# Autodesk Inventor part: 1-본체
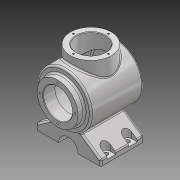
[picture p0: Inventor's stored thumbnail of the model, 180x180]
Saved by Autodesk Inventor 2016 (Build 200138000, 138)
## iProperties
Created: 2017-04
Part Number: 1-본체
Material: 알루미늄 6061
Document SubType Name: Modeling
Designer: H
Density: 2.7 g/cm^3
Appearance: 알루미늄 - 평지
Mass: 1664.44 g
Surface Area: 1066.89 cm^2
Volume: 616.46 cm^3
Author: H
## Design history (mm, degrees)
sketch "스케치2"
  geometry: L1 (-54, 50)-(54, 50); L2 (54, 50)-(54, 0); L3 (54, 0)-(-54, 0); L4 (-54, 0)-(-54, 50); A1 r 113 centre (-59, 0) between (54, 0) and (42.336, 50); 2 further points
  constraints: 8 end point, 2 parallel, 2 point on circle, 2 point on line, 1 centre point, 1 coincident, 1 horizontal, 1 midpoint, 1 perpendicular
  dimensions: "d1" = 113 radius of A1; "d2" = 100 diameter of L1 L3; "d128" = 108 horizontal distance of L2.end L1.start
revolve "회전1" sketch "스케치2" stored, may be unused: angle "d3" = 90 deg
node "작업 평면1"
sketch "스케치4"
  geometry: L1 (50, -54)-(-50, -54) reference; C1 r 38 at (0, -4); 2 further points
  constraints: 1 centre point, 1 midpoint, 1 vertical alignment
  dimensions: "d8" = 50 distance from line of L1 C1.centre; "d9" = 76 diameter of C1
extrude "돌출2" join sketch "스케치4" stored distance "d10" = 10; taper "d11" = 0 deg
sketch "스케치5"
  geometry: C1 r 38 at (0, 0); C2 r 50 at (0, 0) reference; 1 further point
  constraints: 1 centre point, 1 coincident
  dimensions: "d12" = 76 diameter of C1
extrude "돌출3" join sketch "스케치5" distance "d13" = 12; taper "d14" = 0 deg
node "작업 평면2"
sketch "스케치6"
  geometry: L1 (-60, -72)-(60, -72); L2 (60, -72)-(60, -82); L3 (60, -82)-(-60, -82); L4 (-60, -82)-(-60, -72); L5 (-60, -72)-(-5.876, -34.102); L6 (-5.876, -34.102)-(5.876, -34.102); L7 (5.876, -34.102)-(60, -72); C1 r 50 at (0, 0) reference; 2 further points
  constraints: 14 end point, 2 horizontal, 2 parallel, 1 equal length, 1 midpoint, 1 perpendicular, 1 vertical alignment
  dimensions: "d16" = 10 distance of L1.end L2.end; "d17" = 82 distance from line of point (0, 0) L3; "d18" = 120 distance of L2.end L3.end; "d19" = 55 deg angle of L4 L5; "d20" = 37.89801 distance between parallel lines of L1 L6
extrude "돌출4" join sketch "스케치6" distance "d21" = 80; taper "d22" = 0 deg
sketch "스케치7"
  geometry: L1 (-54, 50)-(42.336, 50) reference; L2 (-54, -50)-(42.336, -50) reference; L3 (-54, -50)-(-54, 50) reference; L4 (-44, 0)-(54, 0); L5 (35.916, 40)-(-44, 40); L6 (-44, 40)-(-44, 0); A1 r 113 centre (-59, 0) between (42.336, -50) and (42.336, 50) reference; A2 r 103 centre (-59, 0) between (44, 0) and (35.916, 40); 1 further point
  constraints: 7 end point, 4 point on circle, 2 point on line, 1 centre point, 1 other
  dimensions: "d24" = 10 distance between parallel lines of L1 L5; "d25" = 10 radial gap between concentric circles of A1 A2; "d26" = 98 distance of L4.start L4.end
revolve "회전2" sketch "스케치7" stored, may be unused: angle "d27" = 90 deg
hole "구멍1" diameter "d30" = 54; stored, may be unused: countersink angle "d34" = 90 deg, drill point angle "d36" = 118 deg; dims "d28" = 10, "d29" = 10, "d31" = 6, "d32" = 4, "d33" = 2, "d35" = 8
hole "구멍2" diameter "d39" = 54; stored, may be unused: countersink angle "d43" = 90 deg, drill point angle "d45" = 118 deg; dims "d37" = 10, "d38" = 10, "d40" = 6, "d41" = 4, "d42" = 2, "d44" = 8
sketch "스케치8"
  geometry: L1 (0, 0)-(0, -32.5); C1 r 38 at (0, 0) reference; 1 further point
  constraints: 2 end point, 1 vertical
  dimensions: "d46" = 32.5 distance of L1.start L1.end
hole "구멍3" sketch "스케치8" at (0, -32.5) diameter "d47" = 3.242; stored, may be unused: countersink angle "d51" = 90 deg, drill point angle "d53" = 118 deg; dims "d48" = 8, "d49" = 4, "d50" = 2, "d52" = 10
sketch "스케치9"
  geometry: L1 (0, 0)-(0, 32.5); C1 r 38 at (0, 0) reference; 1 further point
  constraints: 2 end point, 1 vertical
  dimensions: "d57" = 32.5 distance of L1.start L1.end
hole "구멍4" sketch "스케치9" at (0, 32.5) diameter "d58" = 3.242; stored, may be unused: countersink angle "d62" = 90 deg, drill point angle "d64" = 118 deg; dims "d59" = 8, "d60" = 4, "d61" = 2, "d63" = 10
sketch "스케치10"
  geometry: L1 (-60, -82)-(60, -82) reference; C1 r 18 at (0, -82); 1 further point
  constraints: 1 centre point, 1 midpoint
  dimensions: "d69" = 18 radius of C1
extrude "돌출5" cut sketch "스케치10" stored distance "d70" = 80; taper "d71" = 0 deg
node "작업 평면3"
sketch "스케치11"
  geometry: L1 (60, -46)-(60, 34) reference; L2 (18, -46)-(-18, -46) reference; L3 (50, 14)-(-50, 14); L4 (-50, 14)-(-50, -26); L5 (-50, -26)-(50, -26); L6 (50, -26)-(50, 14); L7 (-50, 14)-(-60, 14); L8 (-50, 22)-(-60, 22); L9 (-60, 6)-(-50, 6); L10 (-60, -46)-(-60, 34) reference; L11 (-50, -26)-(-60, -26); L12 (-50, -18)-(-60, -18); L13 (-60, -34)-(-50, -34); L14 (50, 14)-(60, 14); L15 (50, 6)-(60, 6); L16 (60, 22)-(50, 22); L17 (50, -26)-(60, -26); L18 (50, -34)-(60, -34); L19 (60, -18)-(50, -18); A1 r 8 centre (-50, 14) between (-50, 6) and (-50, 22); A2 r 8 centre (-60, 14) between (-60, 22) and (-60, 6); A3 r 8 centre (-50, -26) between (-50, -34) and (-50, -18); A4 r 8 centre (-60, -26) between (-60, -18) and (-60, -34); A5 r 8 centre (50, 14) between (50, 22) and (50, 6); A6 r 8 centre (60, 14) between (60, 6) and (60, 22); A7 r 8 centre (50, -26) between (50, -18) and (50, -34); A8 r 8 centre (60, -26) between (60, -34) and (60, -18); 9 further points
  constraints: 40 end point, 16 point on circle, 16 tangent, 8 centre point, 8 midpoint, 7 point on line, 6 parallel, 2 horizontal, 1 horizontal alignment, 1 perpendicular, 1 vertical alignment
  dimensions: "d73" = 40 distance of L5.end L3.start; "d74" = 100 distance of L4.end L5.end; "d75" = 8 radius of A2; "d76" = 8 radius of A4; "d77" = 8 radius of A6; "d78" = 8 radius of A8
extrude "돌출6" cut sketch "스케치11" distance "d79" = 24.75; taper "d80" = 0 deg
hole "구멍5" diameter "d83" = 8; stored, may be unused: countersink angle "d87" = 90 deg, drill point angle "d89" = 118 deg; dims "d81" = 10, "d82" = 10, "d84" = 8, "d85" = 4, "d86" = 2, "d88" = 10
hole "구멍6" diameter "d92" = 8; stored, may be unused: countersink angle "d96" = 90 deg, drill point angle "d98" = 118 deg; dims "d90" = 10, "d91" = 10, "d93" = 8, "d94" = 4, "d95" = 2, "d97" = 10
hole "구멍7" diameter "d101" = 8; stored, may be unused: countersink angle "d105" = 90 deg, drill point angle "d107" = 118 deg; dims "d99" = 10, "d100" = 10, "d102" = 8, "d103" = 4, "d104" = 2, "d106" = 10
hole "구멍8" diameter "d110" = 8; stored, may be unused: countersink angle "d114" = 90 deg, drill point angle "d116" = 118 deg; dims "d108" = 10, "d109" = 10, "d111" = 8, "d112" = 4, "d113" = 2, "d115" = 10
node "작업 평면4"
sketch "스케치12"
  geometry: C1 r 50 at (0, 0) reference; 2 further points
  constraints: 1 coincident, 1 other
feature "엠보싱1" sketch "스케치12" dims "d13" = 12, "d14" = 0, "d118" = 0.5, "d119" = 0
fillet "모깎기1" dims "d120" = 3
chamfer "모따기1" distance "d121" = 1; stored, may be unused: second distance "d122" = 2, angle "d123" = 45 deg
fillet "모깎기2" dims "d124" = 3
fillet "모깎기3" dims "d125" = 3
fillet "모깎기4" dims "d126" = 3
fillet "모깎기5" dims "d127" = 3
node "솔리드1"
pattern_circular "원형 패턴1" dims angle "d55" = 360 deg
pattern_circular "원형 패턴2" dims angle "d66" = 360 deg
other parameters: "d4" = 65, "d15" = -8, "d72" = -51.25, "d117" = 82.5
